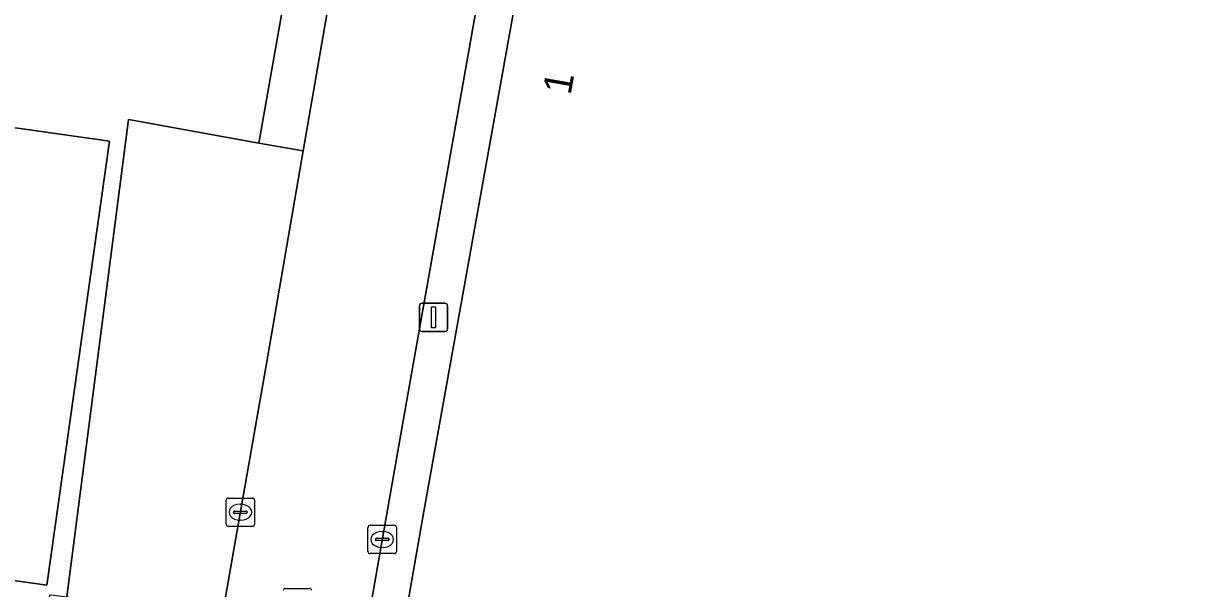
# Model space of a CAD drawing. Extents: x 161402 to 161933, y 381647 to 382315.
# Drawn here: x 161828.37 to 161869.86, y 382056.02 to 382075.91 of the extents above; entities that cross this region are included whole.
import ezdxf

# ---------------------------------------------------------------- set-up
doc = ezdxf.new("R2010")
doc.units = 0
for name, color, linetype in [('IMGEO_Erf', 7, 'Continuous'), ('IMGEO_Kolk', 7, 'Continuous'), ('IMGEO_Lichtmast', 7, 'Continuous'), ('IMGEO_Pand', 7, 'Continuous'), ('IMGEO_Pand_nummerreeks', 7, 'Continuous'), ('IMGEO_Parkeervlak_gesloten', 7, 'Continuous'), ('IMGEO_Rijbaan_lokaal_open', 7, 'Continuous'), ('IMGEO_Rioolput', 7, 'Continuous'), ('IMGEO_Voetpad_gesloten', 7, 'Continuous')]:
    doc.layers.add(name, color=color, linetype=linetype)

msp = doc.modelspace()

# ---------------------------------------------------------------- linework, layer by layer
at = {"layer": 'IMGEO_Erf'}
msp.add_lwpolyline([(161781.596, 381964.647), (161815.795, 381959.903), (161829.294, 382055.793), (161829.439, 382055.781), (161829.897, 382055.72), (161832.064, 382072.53), (161836.652, 382071.701), (161840.585, 382094.002)], dxfattribs=at)
msp.add_lwpolyline([(161818.628, 382073.569), (161831.398, 382071.764), (161829.188, 382056.128), (161823.277, 382056.963), (161825.212, 382070.66), (161818.354, 382071.629)], close=True, dxfattribs=at)
at = {"layer": 'IMGEO_Kolk'}
for p, q in [((161835.503, 382058.274), (161835.503, 382059.126)), ((161835.578, 382059.2), (161836.43, 382059.2)), ((161835.991, 382058.98), (161836.016, 382058.98)), ((161836.504, 382059.126), (161836.504, 382058.274)), ((161835.762, 382058.694), (161835.762, 382058.706)), ((161836.2, 382058.657), (161835.802, 382058.657)), ((161835.805, 382058.743), (161836.203, 382058.743)), ((161836.246, 382058.706), (161836.246, 382058.694)), ((161836.43, 382058.2), (161835.578, 382058.2)), ((161836.014, 382058.42), (161835.989, 382058.42)), ((161840.494, 382057.316), (161840.494, 382058.168)), ((161840.569, 382058.242), (161841.421, 382058.242)), ((161841.495, 382058.168), (161841.495, 382057.316)), ((161840.753, 382057.736), (161840.753, 382057.748)), ((161841.191, 382057.699), (161840.793, 382057.699)), ((161840.796, 382057.785), (161841.194, 382057.785)), ((161840.982, 382058.022), (161841.007, 382058.022)), ((161841.237, 382057.748), (161841.237, 382057.736)), ((161841.421, 382057.242), (161840.569, 382057.242)), ((161841.005, 382057.462), (161840.98, 382057.462))]:
    msp.add_line(p, q, dxfattribs=at)
for points in [[(161835.503, 382058.274), (161835.503, 382059.126)], [(161835.578, 382059.2), (161836.43, 382059.2)], [(161836.504, 382059.126), (161836.504, 382058.274)], [(161836.43, 382058.2), (161835.578, 382058.2)], [(161840.494, 382057.316), (161840.494, 382058.168)], [(161840.569, 382058.242), (161841.421, 382058.242)], [(161841.495, 382058.168), (161841.495, 382057.316)], [(161841.421, 382057.242), (161840.569, 382057.242)]]:
    msp.add_lwpolyline(points, dxfattribs=at)
for centre, radius, start, end in [((161835.58, 382059.124), 0.0765, 91.552, 178.448), ((161835.58, 382059.124), 0.0765, 91.552, 178.448), ((161836.428, 382059.124), 0.0765, 1.552, 88.448), ((161836.428, 382059.124), 0.0765, 1.552, 88.448), ((161835.802, 382058.703), 0.0403, 85.8775, 175.7526), ((161835.799, 382058.693), 0.0366, 178.938, 274.7102), ((161836.203, 382058.7), 0.043, 264.8664, 352.4533), ((161836.207, 382058.705), 0.0386, 1.7309, 96.639), ((161835.58, 382058.276), 0.0765, 181.552, 268.448), ((161835.58, 382058.276), 0.0765, 181.552, 268.448), ((161836.428, 382058.276), 0.0765, 271.552, 358.448), ((161836.428, 382058.276), 0.0765, 271.552, 358.448), ((161840.571, 382058.166), 0.0765, 91.552, 178.448), ((161840.571, 382058.166), 0.0765, 91.552, 178.448), ((161841.419, 382058.166), 0.0765, 1.552, 88.448), ((161841.419, 382058.166), 0.0765, 1.552, 88.448), ((161840.793, 382057.745), 0.0403, 85.8775, 175.7526), ((161840.79, 382057.735), 0.0366, 178.938, 274.7102), ((161841.194, 382057.742), 0.043, 264.8664, 352.4533), ((161841.198, 382057.747), 0.0386, 1.7309, 96.639), ((161840.571, 382057.318), 0.0765, 181.552, 268.448), ((161840.571, 382057.318), 0.0765, 181.552, 268.448), ((161841.419, 382057.318), 0.0765, 271.552, 358.448), ((161841.419, 382057.318), 0.0765, 271.552, 358.448)]:
    msp.add_arc(centre, radius, start, end, dxfattribs=at)
for centre, major_axis, ratio, start_param, end_param in [((161835.99, 382058.7), (-0.387, 0.002), 0.722429, 4.712389, 7.853982), ((161836.015, 382058.7), (-0.39, 0.002), 0.717154, 1.570796, 4.712389), ((161840.981, 382057.742), (-0.387, 0.002), 0.722429, 4.712389, 7.853982), ((161841.006, 382057.742), (-0.39, 0.002), 0.717154, 1.570796, 4.712389)]:
    msp.add_ellipse(centre, major_axis=major_axis, ratio=ratio, start_param=start_param, end_param=end_param, dxfattribs=at)
at = {"layer": 'IMGEO_Lichtmast'}
for p, q in [((161842.304, 382065.163), (161842.304, 382065.963)), ((161842.304, 382065.963), (161842.304, 382065.163)), ((161842.404, 382066.063), (161843.194, 382066.063)), ((161843.194, 382066.063), (161842.404, 382066.063)), ((161843.294, 382065.963), (161843.294, 382065.163)), ((161843.294, 382065.163), (161843.294, 382065.963)), ((161843.194, 382065.063), (161842.404, 382065.063)), ((161842.404, 382065.063), (161843.194, 382065.063))]:
    msp.add_line(p, q, dxfattribs=at)
msp.add_lwpolyline([(161842.724, 382065.938), (161842.874, 382065.938), (161842.874, 382065.188), (161842.724, 382065.188), (161842.724, 382065.938)], dxfattribs=at)
for centre, start, end in [((161842.404, 382065.963), 90, 180), ((161842.404, 382065.963), 90, 180), ((161843.194, 382065.963), 0, 90), ((161843.194, 382065.963), 360, 90), ((161842.404, 382065.163), 180, 270), ((161842.404, 382065.163), 180, 270), ((161843.194, 382065.163), 270, 0), ((161843.194, 382065.163), 270, 0)]:
    msp.add_arc(centre, 0.1, start, end, dxfattribs=at)
at = {"layer": 'IMGEO_Pand'}
for points in [[(161881.604, 382083.709), (161864.747, 382086.071), (161864.705, 382087.108), (161857.022, 382088.5), (161857.282, 382089.936), (161856.514, 382090.075), (161856.605, 382090.577), (161849.637, 382091.837), (161848.409, 382092.059), (161845.824, 382077.508), (161842.463, 382058.722), (161841.73, 382054.571), (161852.314, 382052.645), (161867.831, 382049.852), (161874.803, 382048.597), (161875.966, 382054.535), (161876.056, 382054.517), (161876.327, 382055.897), (161879.777, 382073.754), (161879.674, 382073.772), (161879.866, 382074.825), (161879.984, 382074.802), (161880.941, 382079.709), (161880.846, 382079.728)], [(161818.628, 382073.569), (161818.354, 382071.629), (161825.212, 382070.66), (161823.277, 382056.963), (161829.188, 382056.128), (161831.398, 382071.764)]]:
    msp.add_lwpolyline(points, close=True, dxfattribs=at)
at = {"layer": 'IMGEO_Parkeervlak_gesloten'}
msp.add_lwpolyline([(161836.914, 382063.862), (161838.217, 382071.422), (161836.652, 382071.701), (161832.064, 382072.53), (161829.897, 382055.72), (161835.352, 382054.98)], close=True, dxfattribs=at)
at = {"layer": 'IMGEO_Rijbaan_lokaal_open'}
for points in [[(161840.202, 382046.042), (161841.73, 382054.571), (161842.463, 382058.722), (161845.824, 382077.508), (161848.409, 382092.059), (161849.637, 382091.837), (161850.155, 382094.961), (161849.74, 382095.198), (161861.265, 382106.705), (161864.069, 382106.453), (161863.229, 382133.182), (161861.825, 382133.473), (161862.193, 382125.995), (161862.49, 382119.308), (161862.638, 382116.087)], [(161859.869, 382107.508), (161855.583, 382102.928), (161847.522, 382094.137), (161844.797, 382079.199), (161841.729, 382061.924), (161839.275, 382047.946), (161836.784, 382033.46), (161833.899, 382016.966), (161830.695, 382000), (161827.554, 381983.498), (161825.196, 381970.616), (161825.164, 381970.44), (161822.54, 381956.991), (161822.45, 381956.505), (161823.681, 381955.575), (161824.173, 381957.682), (161825.719, 381965.932), (161826.684, 381971.203), (161827.883, 381977.756), (161828.609, 381981.506), (161828.968, 381983.243), (161830.987, 381994.574), (161831.954, 382000), (161840.202, 382046.042)], [(161839.275, 382047.946), (161841.729, 382061.924), (161844.797, 382079.199), (161847.522, 382094.137), (161855.583, 382102.928), (161859.869, 382107.508)], [(161840.146, 382082.597), (161838.823, 382074.942), (161838.217, 382071.422), (161836.914, 382063.862), (161835.352, 382054.98), (161834.774, 382051.699), (161834.543, 382050.384), (161830.73, 382029.273), (161829.195, 382020.232)]]:
    msp.add_lwpolyline(points, dxfattribs=at)
at = {"layer": 'IMGEO_Rioolput'}
msp.add_line((161837.589, 382056.016), (161838.441, 382056.016), dxfattribs=at)
msp.add_lwpolyline([(161837.589, 382056.016), (161838.441, 382056.016)], dxfattribs=at)
for centre, start, end in [((161837.591, 382055.94), 91.552, 178.448), ((161837.591, 382055.94), 91.552, 178.448), ((161838.439, 382055.94), 1.552, 88.448), ((161838.439, 382055.94), 1.552, 88.448)]:
    msp.add_arc(centre, 0.0765, start, end, dxfattribs=at)
at = {"layer": 'IMGEO_Voetpad_gesloten'}
msp.add_lwpolyline([(161840.585, 382094.002), (161836.652, 382071.701), (161838.217, 382071.422), (161838.823, 382074.942), (161840.146, 382082.597)], dxfattribs=at)

# ---------------------------------------------------------------- texts
at = {"layer": 'IMGEO_Pand_nummerreeks'}
msp.add_text('1', height=1, rotation=79.8589, dxfattribs=at).set_placement((161847.622, 382073.366))

doc.saveas('drawing.dxf')
